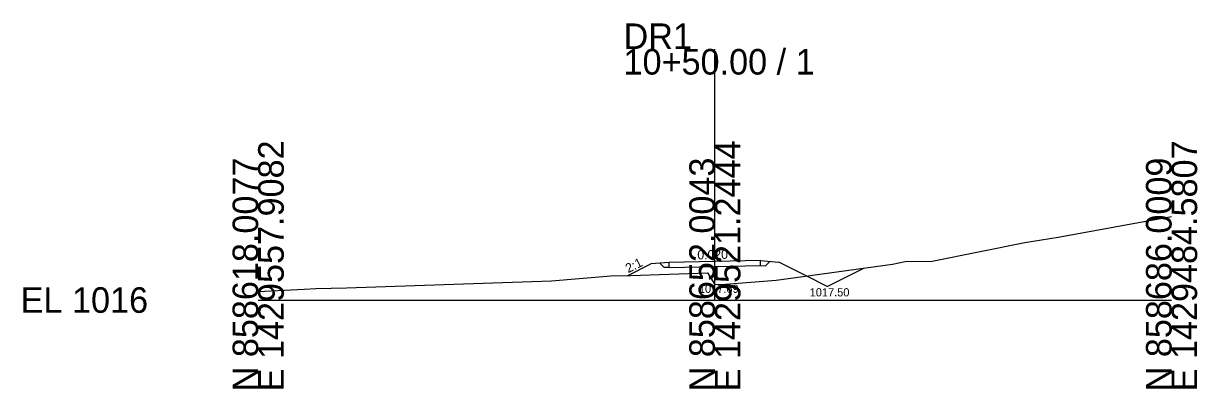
# Model space of a CAD drawing. Extents: x -26 to 103, y -10 to 1022.
# Drawn here: x -25.7 to 102.8, y 490.3 to 530.3 of the extents above; entities that cross this region are included whole.
import ezdxf

# ---------------------------------------------------------------- set-up
doc = ezdxf.new("R2010")
doc.units = 0
for name, color, linetype in [('Default', 7, 'Continuous'), ('Exist Cross Section Cell', 7, 'Continuous'), ('Exist XS Center Line Elevation Label', 7, 'Continuous'), ('Exist XS Ground Line', 7, 'Continuous'), ('Prop CMT Pvmt Surface', 7, 'Continuous'), ('Prop CMT Shld Paved Course 1', 7, 'Continuous'), ('Prop CMT Slope Grass', 7, 'Continuous'), ('Prop CMT Subgrade Earthwork', 7, 'Continuous'), ('Prop CMT Template Flag', 7, 'Continuous'), ('Prop XS SE Text', 7, 'Continuous'), ('Prop XS Side Slope Text', 7, 'Continuous')]:
    doc.layers.add(name, color=color, linetype=linetype)

msp = doc.modelspace()

# ---------------------------------------------------------------- linework, layer by layer
at = {"layer": 'Exist Cross Section Cell'}
for p, q in [((50, 500), (50, 527.5)), ((0, 500), (50, 500)), ((50, 500), (100, 500))]:
    msp.add_line(p, q, dxfattribs=at)
at = {"layer": 'Exist XS Ground Line'}
msp.add_lwpolyline([(0, 500.93), (5.05, 501.21), (6.3, 501.28), (9.66, 501.34), (32.13, 502.11), (38.62, 502.64), (40.79, 502.7), (49.19, 502.97), (50, 501.69), (51.16, 501.74), (56.72, 502.16), (69.44, 503.94), (70.83, 504.22), (73.8, 504.26), (83.92, 506.3), (87.57, 506.89), (100, 509.17)], dxfattribs=at)
at = {"layer": 'Prop CMT Pvmt Surface'}
msp.add_line((50, 504.22), (45, 504.12), dxfattribs=at)
msp.add_lwpolyline([(55, 504.32), (50, 504.22)], dxfattribs=at)
at = {"layer": 'Prop CMT Shld Paved Course 1'}
for points in [[(45, 503.57), (45, 504.12)], [(55, 503.77), (55, 504.32)]]:
    msp.add_lwpolyline(points, dxfattribs=at)
at = {"layer": 'Prop CMT Slope Grass'}
for p, q in [((40.48, 502.7), (43, 503.96)), ((55, 504.32), (57, 504.16)), ((60.06, 502.63), (57, 504.16)), ((62.31, 501.5), (60.06, 502.63)), ((62.31, 501.5), (66.32, 503.5))]:
    msp.add_line(p, q, dxfattribs=at)
msp.add_lwpolyline([(45, 504.12), (43, 503.96)], dxfattribs=at)
at = {"layer": 'Prop CMT Subgrade Earthwork'}
for points in [[(44.45, 503.56), (43.98, 504.03)], [(55.55, 503.76), (56.02, 504.23)], [(45, 503.57), (44.45, 503.56)], [(55, 503.77), (55.55, 503.76)]]:
    msp.add_lwpolyline(points, dxfattribs=at)
at = {"layer": 'Prop CMT Template Flag'}
msp.add_line((45, 503.57), (50, 503.67), dxfattribs=at)
msp.add_lwpolyline([(50, 503.67), (55, 503.77)], dxfattribs=at)

# ---------------------------------------------------------------- texts
at = {"layer": 'Default'}
msp.add_text('1017.50', height=0.9, dxfattribs=at).set_placement((60.38, 500.4))
at = {"layer": 'Exist Cross Section Cell'}
for s, p in [('DR1', (40, 527.5)), ('10+50.00 / 1', (40, 524.7)), ('EL 1016', (-26, 498.6))]:
    msp.add_text(s, height=2.8, dxfattribs=at).set_placement(p)
for s, p in [('E 1429557.9082', (2.8, 490)), ('E 1429521.2444', (52.8, 490)), ('E 1429484.5807', (102.8, 490)), ('N 858618.0077', (0, 490)), ('N 858652.0043', (50, 490)), ('N 858686.0009', (100, 490))]:
    msp.add_text(s, height=2.8, rotation=90, dxfattribs=at).set_placement(p)
at = {"layer": 'Exist XS Center Line Elevation Label'}
msp.add_text('1017.69', height=0.9, dxfattribs=at).set_placement((48.25, 500.79))
at = {"layer": 'Prop XS SE Text'}
msp.add_text('0.020', height=1, rotation=1.1458, dxfattribs=at).set_placement((48.09, 504.45))
at = {"layer": 'Prop XS Side Slope Text'}
msp.add_text('2:1', height=1, rotation=26.5651, dxfattribs=at).set_placement((40.52, 502.95))

doc.saveas('drawing.dxf')
